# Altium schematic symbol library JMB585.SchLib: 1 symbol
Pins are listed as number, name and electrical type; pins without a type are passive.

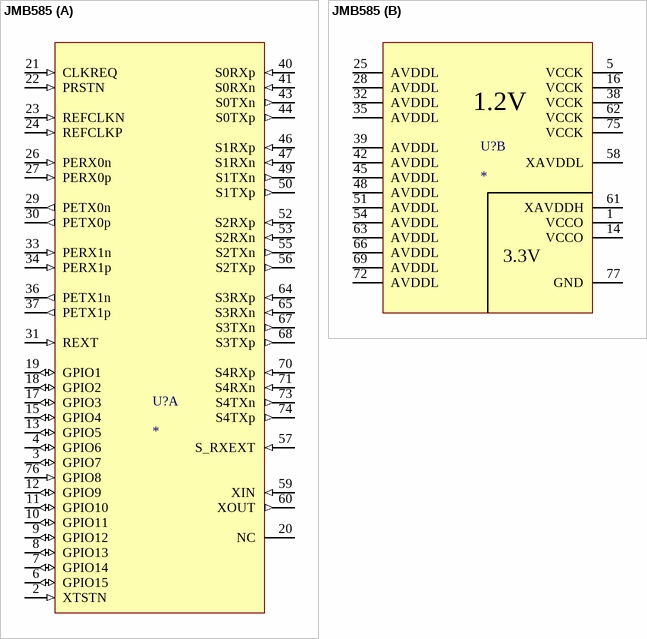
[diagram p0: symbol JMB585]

## JMB585
designator U?
footprint QFN76-9X9
part A pins: 2 XTSTN (in), 3 GPIO7 (io), 4 GPIO6 (io), 6 GPIO15 (io), 7 GPIO14 (io), 8 GPIO13 (io), 9 GPIO12 (io), 10 GPIO11 (io), 11 GPIO10 (io), 12 GPIO9 (io), 13 GPIO5 (io), 15 GPIO4 (io), 17 GPIO3 (io), 18 GPIO2 (io), 19 GPIO1 (io), 20 NC, 21 CLKREQ (in), 22 PRSTN (in), 23 REFCLKN (in), 24 REFCLKP (in), 26 PERX0n (in), 27 PERX0p (in), 29 PETX0n (out), 30 PETX0p (out), 31 REXT (in), 33 PERX1n (in), 34 PERX1p (in), 36 PETX1n (out), 37 PETX1p (out), 40 S0RXp (in), 41 S0RXn (in), 43 S0TXn (out), 44 S0TXp (out), 46 S1RXp (in), 47 S1RXn (in), 49 S1TXn (out), 50 S1TXp (out), 52 S2RXp (in), 53 S2RXn (in), 55 S2TXn (out), 56 S2TXp (out), 57 S_RXEXT (in), 59 XIN (in), 60 XOUT (out), 64 S3RXp (in), 65 S3RXn (in), 67 S3TXn (out), 68 S3TXp (out), 70 S4RXp (in), 71 S4RXn (in), 73 S4TXn (out), 74 S4TXp (out), 76 GPIO8 (in)
part B pins: 1 VCCO (power), 5 VCCK (power), 14 VCCO (power), 16 VCCK (power), 25 AVDDL (power), 28 AVDDL (power), 32 AVDDL (power), 35 AVDDL (power), 38 VCCK (power), 39 AVDDL (power), 42 AVDDL (power), 45 AVDDL (power), 48 AVDDL (power), 51 AVDDL (power), 54 AVDDL (power), 58 XAVDDL (power), 61 XAVDDH (power), 62 VCCK (power), 63 AVDDL (power), 66 AVDDL (power), 69 AVDDL (power), 72 AVDDL (power), 75 VCCK (power), 77 GND (power)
